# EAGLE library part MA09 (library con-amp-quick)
AMP QUICK CONNECTOR
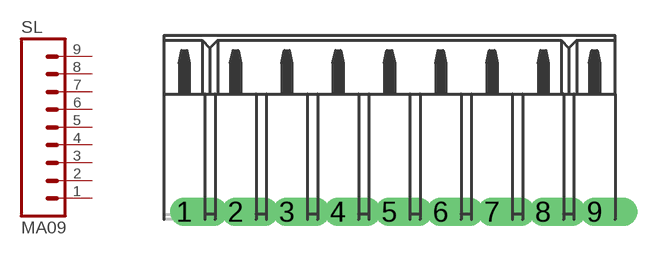
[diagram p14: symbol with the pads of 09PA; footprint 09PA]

Designator prefix SL

## MA09  [09PA]
1  1  pas
2  2  pas
3  3  pas
4  4  pas
5  5  pas
6  6  pas
7  7  pas
8  8  pas
9  9  pas

## Footprint 09PA (pad centres in mm)
AMP QUICK CONNECTOR
drill 0.914 offset: 1 -10.16,0; 2 -7.62,0; 3 -5.08,0; 4 -2.54,0; 5 0,0; 6 2.54,0; 7 5.08,0; 8 7.62,0; 9 10.16,0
